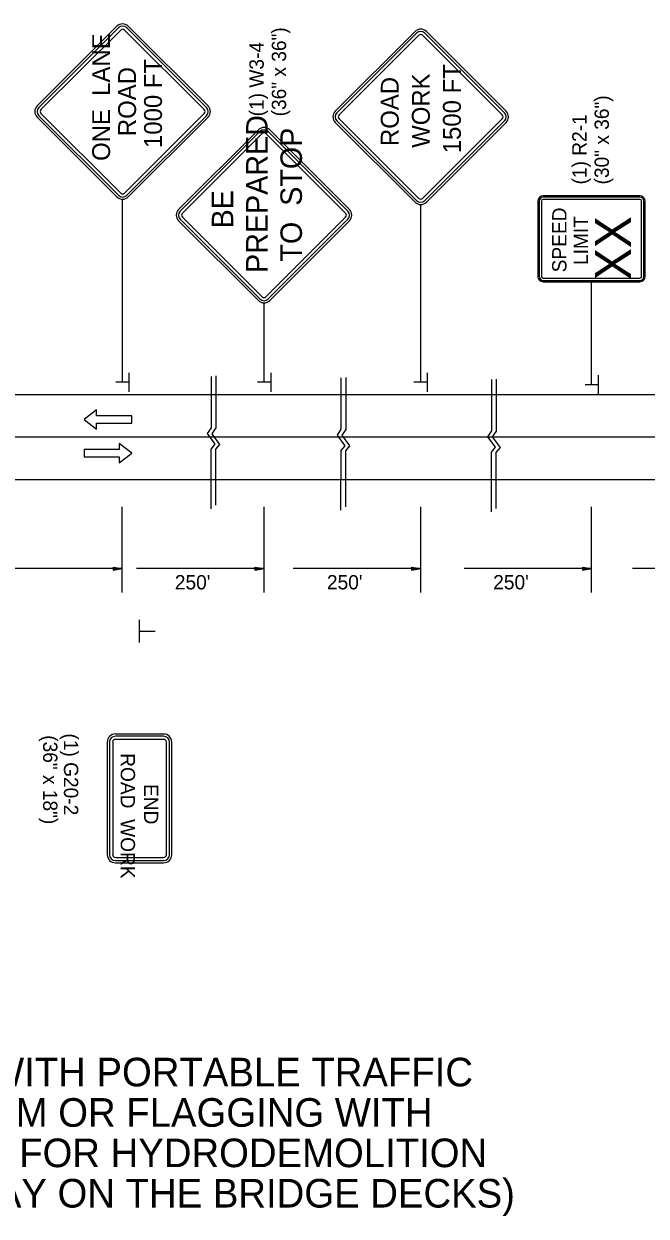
# Model space of a CAD drawing. Extents: x 1927831 to 1930787, y 596452 to 597699.
# Drawn here: x 1928082 to 1928342, y 596693 to 597193 of the extents above; entities that cross this region are included whole.
import ezdxf

# ---------------------------------------------------------------- set-up
doc = ezdxf.new("R2010")
doc.units = 0
for name, color, linetype in [('Default', 7, 'Continuous'), ('P_TC_Signs_Permanent', 7, 'Continuous'), ('P_TC_Signs_Temporary', 7, 'Continuous'), ('R_Border', 7, 'Continuous'), ('R_Striping', 7, 'Continuous')]:
    doc.layers.add(name, color=color, linetype=linetype)

msp = doc.modelspace()

# ---------------------------------------------------------------- linework, layer by layer
at = {"layer": 'Default'}
for p, q in [((1928125.55, 597042.44), (1928120.09, 597042.44)), ((1928125.67, 597046.42), (1928125.67, 597038.42)), ((1928185.01, 597042.44), (1928179.54, 597042.44)), ((1928185.12, 597046.42), (1928185.12, 597038.42)), ((1928250.48, 597042.44), (1928245.02, 597042.44)), ((1928250.6, 597046.42), (1928250.6, 597038.42)), ((1928322.37, 597045.39), (1928322.37, 597037.38)), ((1927841.07, 597037.34), (1928485.68, 597037.29)), ((1928322.25, 597041.41), (1928316.79, 597041.41)), ((1927840.35, 597019.55), (1928622.79, 597019.49)), ((1927840.85, 597001.76), (1928485.68, 597001.71)), ((1928122.82, 596954.25), (1928122.82, 596990.28)), ((1928182.27, 596954.25), (1928182.27, 596990.28)), ((1928247.93, 596954.25), (1928247.93, 596990.28)), ((1928319.52, 596954.25), (1928319.52, 596990.28)), ((1928122.82, 596964.29), (1928023.06, 596964.29)), ((1928118.98, 596964.87), (1928122.82, 596964.29)), ((1928118.98, 596964.87), (1928118.98, 596963.71)), ((1928118.98, 596964.77), (1928122.18, 596964.29)), ((1928118.98, 596964.67), (1928121.52, 596964.29)), ((1928118.98, 596964.58), (1928120.88, 596964.29)), ((1928118.98, 596964.48), (1928120.23, 596964.29)), ((1928118.98, 596964.38), (1928119.59, 596964.29)), ((1928118.98, 596963.71), (1928122.82, 596964.29)), ((1928118.98, 596964.1), (1928120.23, 596964.29)), ((1928118.98, 596963.91), (1928121.52, 596964.29)), ((1928118.98, 596963.81), (1928122.18, 596964.29)), ((1928118.98, 596964), (1928120.88, 596964.29)), ((1928118.98, 596964.2), (1928119.59, 596964.29)), ((1928182.27, 596964.29), (1928128.87, 596964.29)), ((1928178.44, 596964.87), (1928182.27, 596964.29)), ((1928178.44, 596964.87), (1928178.44, 596963.71)), ((1928178.44, 596964.77), (1928181.63, 596964.29)), ((1928178.44, 596964.67), (1928180.97, 596964.29)), ((1928178.44, 596964.58), (1928180.33, 596964.29)), ((1928178.44, 596964.48), (1928179.68, 596964.29)), ((1928178.44, 596964.38), (1928179.04, 596964.29)), ((1928178.44, 596963.71), (1928182.27, 596964.29)), ((1928178.44, 596964.1), (1928179.68, 596964.29)), ((1928178.44, 596963.91), (1928180.97, 596964.29)), ((1928178.44, 596963.81), (1928181.63, 596964.29)), ((1928178.44, 596964), (1928180.33, 596964.29)), ((1928178.44, 596964.2), (1928179.04, 596964.29)), ((1928247.93, 596964.29), (1928194.52, 596964.29)), ((1928244.09, 596964.87), (1928247.93, 596964.29)), ((1928244.09, 596964.87), (1928244.09, 596963.71)), ((1928244.09, 596964.77), (1928247.29, 596964.29)), ((1928244.09, 596964.67), (1928246.63, 596964.29)), ((1928244.09, 596964.58), (1928245.99, 596964.29)), ((1928244.09, 596964.48), (1928245.34, 596964.29)), ((1928244.09, 596964.38), (1928244.7, 596964.29)), ((1928244.09, 596963.71), (1928247.93, 596964.29)), ((1928244.09, 596964.1), (1928245.34, 596964.29)), ((1928244.09, 596963.91), (1928246.63, 596964.29)), ((1928244.09, 596963.81), (1928247.29, 596964.29)), ((1928244.09, 596964), (1928245.99, 596964.29)), ((1928244.09, 596964.2), (1928244.7, 596964.29)), ((1928319.52, 596964.29), (1928266.12, 596964.29)), ((1928315.68, 596964.87), (1928319.52, 596964.29)), ((1928315.68, 596964.87), (1928315.68, 596963.71)), ((1928315.68, 596964.77), (1928318.88, 596964.29)), ((1928315.68, 596964.67), (1928318.22, 596964.29)), ((1928315.68, 596964.58), (1928317.58, 596964.29)), ((1928315.68, 596964.48), (1928316.93, 596964.29)), ((1928315.68, 596964.38), (1928316.29, 596964.29)), ((1928315.68, 596963.71), (1928319.52, 596964.29)), ((1928315.68, 596964.1), (1928316.93, 596964.29)), ((1928315.68, 596963.91), (1928318.22, 596964.29)), ((1928315.68, 596963.81), (1928318.88, 596964.29)), ((1928315.68, 596964), (1928317.58, 596964.29)), ((1928315.68, 596964.2), (1928316.29, 596964.29)), ((1928390.13, 596964.29), (1928336.73, 596964.29)), ((1928130.08, 596933.38), (1928130.08, 596942.87)), ((1928130.22, 596938.11), (1928136.7, 596938.11))]:
    msp.add_line(p, q, dxfattribs=at)
for points in [[(1928160.05, 597044.92), (1928160.05, 597023.4), (1928158.39, 597020.93), (1928161.63, 597016.5), (1928159.93, 597014.45), (1928159.92, 596989.43)], [(1928162.1, 597045.12), (1928162.1, 597023.32), (1928160.44, 597020.84), (1928163.67, 597016.41), (1928161.97, 597014.37), (1928161.97, 596990.87)], [(1928214.52, 597044.28), (1928214.52, 597022.75), (1928212.85, 597020.28), (1928216.09, 597015.85), (1928214.39, 597013.81), (1928214.38, 596988.78)], [(1928216.56, 597044.47), (1928216.56, 597022.67), (1928214.9, 597020.2), (1928218.14, 597015.77), (1928216.43, 597013.72), (1928216.43, 596990.22)], [(1928277.56, 597043.61), (1928277.56, 597022.08), (1928275.9, 597019.61), (1928279.13, 597015.18), (1928277.43, 597013.14), (1928277.42, 596988.11)], [(1928279.6, 597043.8), (1928279.6, 597022), (1928277.94, 597019.53), (1928281.18, 597015.1), (1928279.47, 597013.05), (1928279.47, 596989.55)]]:
    msp.add_lwpolyline(points, dxfattribs=at)
at = {"layer": 'P_TC_Signs_Permanent'}
for p, q in [((1928179.89, 597148.33), (1928146.48, 597114.92)), ((1928180.55, 597147.67), (1928147.14, 597114.25)), ((1928181.48, 597146.74), (1928148.07, 597113.33)), ((1928216.48, 597113.33), (1928183.07, 597146.74)), ((1928217.41, 597114.25), (1928184, 597147.67)), ((1928218.07, 597114.92), (1928184.66, 597148.33)), ((1928297.02, 597118.38), (1928297.02, 597086.88)), ((1928297.58, 597118.38), (1928297.58, 597086.88)), ((1928298.52, 597118.38), (1928298.52, 597086.88)), ((1928339.77, 597120.63), (1928299.27, 597120.63)), ((1928339.77, 597120.07), (1928299.27, 597120.07)), ((1928339.77, 597119.13), (1928299.27, 597119.13)), ((1928340.52, 597086.88), (1928340.52, 597118.38)), ((1928341.46, 597086.88), (1928341.46, 597118.38)), ((1928342.02, 597086.88), (1928342.02, 597118.38)), ((1928148.07, 597111.74), (1928181.48, 597078.32)), ((1928183.07, 597078.32), (1928216.48, 597111.74)), ((1928146.48, 597110.14), (1928179.89, 597076.73)), ((1928147.14, 597110.81), (1928180.55, 597077.4)), ((1928184, 597077.4), (1928217.41, 597110.81)), ((1928184.66, 597076.73), (1928218.07, 597110.14)), ((1928299.27, 597086.13), (1928339.77, 597086.13)), ((1928299.27, 597085.19), (1928339.77, 597085.19)), ((1928299.27, 597084.63), (1928339.77, 597084.63))]:
    msp.add_line(p, q, dxfattribs=at)
for centre, radius, start, end in [((1928182.27, 597145.94), 3.37, 45, 135), ((1928182.27, 597145.94), 2.44, 45, 135), ((1928182.27, 597145.94), 1.13, 45, 135), ((1928299.27, 597118.38), 2.25, 90, 180), ((1928299.27, 597118.38), 1.69, 90, 180), ((1928299.27, 597118.38), 0.75, 90, 180), ((1928339.77, 597118.38), 2.25, 360, 90), ((1928339.77, 597118.38), 1.69, 360, 90), ((1928339.77, 597118.38), 0.75, 360, 90), ((1928148.86, 597112.53), 3.37, 135, 225), ((1928148.86, 597112.53), 2.44, 135, 225), ((1928148.86, 597112.53), 1.13, 135, 225), ((1928215.68, 597112.53), 1.13, 315, 45), ((1928215.68, 597112.53), 2.44, 315, 45), ((1928215.68, 597112.53), 3.37, 315, 45), ((1928299.27, 597086.88), 2.25, 180, 270), ((1928299.27, 597086.88), 1.69, 180, 270), ((1928299.27, 597086.88), 0.75, 180, 270), ((1928339.77, 597086.88), 2.25, 270, 360), ((1928339.77, 597086.88), 1.69, 270, 360), ((1928339.77, 597086.88), 0.75, 270, 360), ((1928182.27, 597079.12), 3.37, 225, 315), ((1928182.27, 597079.12), 2.44, 225, 315), ((1928182.27, 597079.12), 1.13, 225, 315)]:
    msp.add_arc(centre, radius, start, end, dxfattribs=at)
at = {"layer": 'P_TC_Signs_Temporary'}
for p, q in [((1928087.2, 597158.38), (1928120.61, 597191.8)), ((1928125.38, 597191.8), (1928158.79, 597158.38)), ((1928087.86, 597157.72), (1928121.27, 597191.13)), ((1928088.79, 597156.79), (1928122.2, 597190.2)), ((1928123.79, 597190.2), (1928157.2, 597156.79)), ((1928124.72, 597191.13), (1928158.13, 597157.72)), ((1928212.13, 597156.16), (1928245.54, 597189.57)), ((1928212.79, 597155.5), (1928246.2, 597188.91)), ((1928213.72, 597154.57), (1928247.13, 597187.98)), ((1928248.72, 597187.98), (1928282.13, 597154.57)), ((1928249.65, 597188.91), (1928283.06, 597155.5)), ((1928250.31, 597189.57), (1928283.72, 597156.16)), ((1928120.61, 597120.2), (1928087.2, 597153.61)), ((1928121.27, 597120.86), (1928087.86, 597154.27)), ((1928122.2, 597121.79), (1928088.79, 597155.2)), ((1928157.2, 597155.2), (1928123.79, 597121.79)), ((1928158.13, 597154.27), (1928124.72, 597120.86)), ((1928158.79, 597153.61), (1928125.38, 597120.2)), ((1928246.2, 597118.64), (1928212.79, 597152.05)), ((1928247.13, 597119.57), (1928213.72, 597152.98)), ((1928282.13, 597152.98), (1928248.72, 597119.57)), ((1928283.06, 597152.05), (1928249.65, 597118.64)), ((1928245.54, 597117.98), (1928212.13, 597151.39)), ((1928283.72, 597151.39), (1928250.31, 597117.98)), ((1928116.58, 596891.56), (1928116.58, 596844.31)), ((1928117.52, 596891.56), (1928117.52, 596844.31)), ((1928118.83, 596891.56), (1928118.83, 596844.31)), ((1928140.2, 596894.93), (1928119.95, 596894.93)), ((1928140.2, 596893.99), (1928119.95, 596893.99)), ((1928140.2, 596892.68), (1928119.95, 596892.68)), ((1928141.33, 596844.31), (1928141.33, 596891.56)), ((1928142.64, 596844.31), (1928142.64, 596891.56)), ((1928143.58, 596844.31), (1928143.58, 596891.56)), ((1928119.95, 596843.18), (1928140.2, 596843.18)), ((1928119.95, 596841.87), (1928140.2, 596841.87)), ((1928119.95, 596840.93), (1928140.2, 596840.93))]:
    msp.add_line(p, q, dxfattribs=at)
for centre, radius, start, end in [((1928122.99, 597189.41), 3.37, 45, 135), ((1928122.99, 597189.41), 2.44, 45, 135), ((1928122.99, 597189.41), 1.12, 45, 135), ((1928247.93, 597187.19), 3.37, 45, 135), ((1928247.93, 597187.19), 2.44, 45, 135), ((1928247.93, 597187.19), 1.12, 45, 135), ((1928089.58, 597156), 3.37, 135, 225), ((1928089.58, 597156), 2.44, 135, 225), ((1928089.58, 597156), 1.13, 135, 225), ((1928156.4, 597156), 1.13, 315, 45), ((1928156.4, 597156), 2.44, 315, 45), ((1928156.4, 597156), 3.37, 315, 45), ((1928214.52, 597153.78), 3.37, 135, 225), ((1928214.52, 597153.78), 2.44, 135, 225), ((1928214.52, 597153.78), 1.13, 135, 225), ((1928281.34, 597153.78), 1.13, 315, 45), ((1928281.34, 597153.78), 2.44, 315, 45), ((1928281.34, 597153.78), 3.37, 315, 45), ((1928122.99, 597122.59), 1.12, 225, 315), ((1928122.99, 597122.59), 3.37, 225, 315), ((1928122.99, 597122.59), 2.44, 225, 315), ((1928247.93, 597120.37), 3.37, 225, 315), ((1928247.93, 597120.37), 2.44, 225, 315), ((1928247.93, 597120.37), 1.12, 225, 315), ((1928119.95, 596891.56), 3.38, 90, 180), ((1928119.95, 596891.56), 2.44, 90, 180), ((1928119.95, 596891.56), 1.13, 90, 180), ((1928140.2, 596891.56), 3.37, 360, 90), ((1928140.2, 596891.56), 2.44, 360, 90), ((1928140.2, 596891.56), 1.13, 360, 90), ((1928119.95, 596844.31), 3.37, 180, 270), ((1928119.95, 596844.31), 2.44, 180, 270), ((1928119.95, 596844.31), 1.13, 180, 270), ((1928140.2, 596844.31), 2.44, 270, 360), ((1928140.2, 596844.31), 1.13, 270, 360), ((1928140.2, 596844.31), 3.38, 270, 360)]:
    msp.add_arc(centre, radius, start, end, dxfattribs=at)
at = {"layer": 'R_Border'}
for p, q in [((1928122.99, 597042.44), (1928122.99, 597119.21)), ((1928247.93, 597042.44), (1928247.93, 597116.99)), ((1928319.52, 597041.41), (1928319.52, 597084.63)), ((1928182.27, 597042.44), (1928182.27, 597075.74))]:
    msp.add_line(p, q, dxfattribs=at)
at = {"layer": 'R_Striping'}
for points in [[(1928112.09, 597030.85), (1928106.9, 597026.85), (1928112.09, 597022.85), (1928112.09, 597025.35), (1928126.8, 597025.35), (1928126.8, 597028.35), (1928112.09, 597028.35)], [(1928121.61, 597008.73), (1928126.8, 597012.73), (1928121.61, 597016.73), (1928121.61, 597014.23), (1928106.9, 597014.23), (1928106.9, 597011.23), (1928121.61, 597011.23)]]:
    msp.add_lwpolyline(points, close=True, dxfattribs=at)

# ---------------------------------------------------------------- texts
at = {"layer": 'Default'}
for s, height, rotation, p in [("250'", 6, 359.9922, (1928144.88, 596955.58)), ("250'", 6, 359.9922, (1928208.62, 596955.59)), ("250'", 6, 359.9922, (1928278.31, 596955.6)), ('LANE CLOSURE WITH PORTABLE TRAFFIC ', 12, 360, (1927938.17, 596747.15)), ('SIGNAL SYSTEM OR FLAGGING WITH ', 12, 360, (1927962.26, 596730.2)), ('TRAFFIC DRUMS FOR HYDRODEMOLITION', 12, 360, (1927944.15, 596713.26)), ('(VAR. CLEAR ROADWAY ON THE BRIDGE DECKS)', 12, 360, (1927903.13, 596696.32))]:
    msp.add_text(s, height=height, rotation=rotation, dxfattribs=at).set_placement(p)
at = {"layer": 'P_TC_Signs_Permanent'}
for s, height, p in [('SPEED', 6, (1928309.02, 597088.56)), ('LIMIT', 6, (1928318.02, 597091.65)), ('XX', 15, (1928336.02, 597085.33))]:
    msp.add_text(s, height=height, rotation=90, dxfattribs=at).set_placement(p)
at = {"layer": 'P_TC_Signs_Temporary'}
for s, height, rotation, p in [('ONE  LANE', 7.5, 90, (1928117.74, 597135.3)), ('1000 FT', 7.5, 90, (1928139.49, 597140.71)), ('ROAD', 7.5, 90, (1928128.62, 597145.69)), ('WORK', 7.5, 90, (1928251.74, 597140.79)), ('1500 FT', 7.5, 90, (1928264.76, 597138.49)), (' ROAD ', 7.5, 90, (1928238.71, 597138.75)), ('PREPARED', 9, 90, (1928183.75, 597088.29)), ('TO  STOP', 9, 90, (1928198.15, 597093.07)), ('BE', 9, 90, (1928169.35, 597106.98)), ('ROAD  WORK', 6, 270, (1928122.2, 596886.89)), ('END', 6, 270, (1928131.95, 596873.96))]:
    msp.add_text(s, height=height, rotation=rotation, dxfattribs=at).set_placement(p)
at = {"layer": 'R_Border'}
for s, height, rotation, p in [('(36" x 36")', 5.9996, 90, (1928191.51, 597153.98)), ('(1) W3-4', 6, 90, (1928182.14, 597153.98)), ('(30" x 36")', 5.9996, 90, (1928326.8, 597125.43)), ('(1) R2-1', 6, 90, (1928317.44, 597125.43)), ('(36" x 18")', 5.9996, 270, (1928089.68, 596894.42)), ('(1) G20-2', 6, 270, (1928098.4, 596895.17))]:
    msp.add_text(s, height=height, rotation=rotation, dxfattribs=at).set_placement(p)

doc.saveas('drawing.dxf')
